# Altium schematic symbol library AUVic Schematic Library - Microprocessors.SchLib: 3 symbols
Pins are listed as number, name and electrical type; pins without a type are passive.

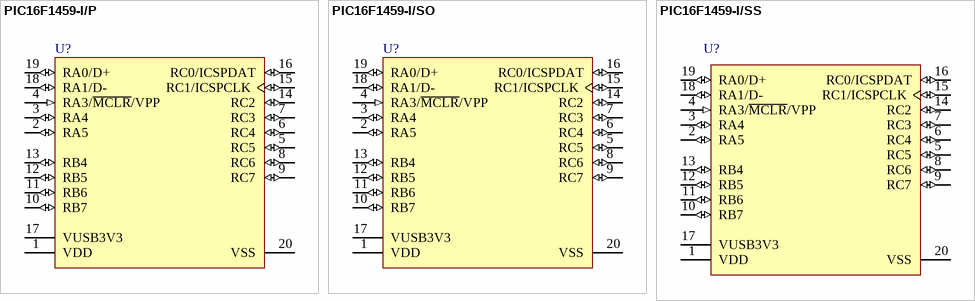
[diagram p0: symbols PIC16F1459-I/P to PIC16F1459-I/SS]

## PIC16F1459-I/P
designator U?
8-Bit Flash USB Microcontroller with XLP Technology, 48 MHz, 14 I/O, -40 to 85 degC, 20-pin PDIP (P20), Tube; Manufacturer: Microchip; PartNumber: PIC16F1459-I/P; # of A/D Channels: 9; Digital Communication: 1 -A/E/USART, 1 -MSSP(SPI/I2C); I/O Pins: 14; Internal Oscillator: 16 MHz, 31 kHz; Max. CPU Speed MHz: 48; Operation Voltage Range: 2.3V - 5.5V; Program Memory KWords: 8; RAM: 1024; Timers: 2 - 8-bit, 1 - 16-bit, 0 - 32-bit
footprint MCHP-PDIP-P20 (DIP, 20-Leads, Body 25.91x6.6mm, Pitch 2.54mm)
pins: 1 VDD (power) "Positive supply.", 2 RA5 (io), 3 RA4 (io), 4 RA3/~{MCLR}/VPP (in), 5 RC5 (io), 6 RC4 (io), 7 RC3 (io), 8 RC6 (io), 9 RC7 (io), 10 RB7 (io), 11 RB6 (io), 12 RB5 (io), 13 RB4 (io), 14 RC2 (io), 15 RC1/ICSPCLK (io), 16 RC0/ICSPDAT (io), 17 VUSB3V3 (power) "Positive supply for USB transceiver.", 18 RA1/D- (io), 19 RA0/D+ (io), 20 VSS (power) "Ground reference."

## PIC16F1459-I/SO
designator U?
8-Bit Flash USB Microcontroller with XLP Technology, 48 MHz, 14 I/O, -40 to 85 degC, 20-pin SOIC (SO20), Tube; Manufacturer: Microchip; PartNumber: PIC16F1459-I/SO; # of A/D Channels: 9; Digital Communication: 1 -A/E/USART, 1 -MSSP(SPI/I2C); I/O Pins: 14; Internal Oscillator: 16 MHz, 31 kHz; Max. CPU Speed MHz: 48; Operation Voltage Range: 2.3V - 5.5V; Program Memory KWords: 8; RAM: 1024; Timers: 2 - 8-bit, 1 - 16-bit, 0 - 32-bit
footprint MCHP-SOIC-SO20_N (SOIC, 20-Leads, Body 12.8x7.5mm, Pitch 1.27mm, IPC Medium Density)
footprint MCHP-SOIC-SO20_L (SOIC, 20-Leads, Body 12.8x7.5mm, Pitch 1.27mm, IPC High Density)
footprint MCHP-SOIC-SO20_M (SOIC, 20-Leads, Body 12.8x7.5mm, Pitch 1.27mm, IPC Low Density)
pins: 1 VDD (power) "Positive supply.", 2 RA5 (io), 3 RA4 (io), 4 RA3/~{MCLR}/VPP (in), 5 RC5 (io), 6 RC4 (io), 7 RC3 (io), 8 RC6 (io), 9 RC7 (io), 10 RB7 (io), 11 RB6 (io), 12 RB5 (io), 13 RB4 (io), 14 RC2 (io), 15 RC1/ICSPCLK (io), 16 RC0/ICSPDAT (io), 17 VUSB3V3 (power) "Positive supply for USB transceiver.", 18 RA1/D- (io), 19 RA0/D+ (io), 20 VSS (power) "Ground reference."

## PIC16F1459-I/SS
designator U?
8-Bit Flash USB Microcontroller with XLP Technology, 48 MHz, 14 I/O, -40 to 85 degC, 20-pin SSOP (SS20), Tube; Manufacturer: Microchip; PartNumber: PIC16F1459-I/SS; # of A/D Channels: 9; Digital Communication: 1 -A/E/USART, 1 -MSSP(SPI/I2C); I/O Pins: 14; Internal Oscillator: 16 MHz, 31 kHz; Max. CPU Speed MHz: 48; Operation Voltage Range: 2.3V - 5.5V; Program Memory KWords: 8; RAM: 1024; Timers: 2 - 8-bit, 1 - 16-bit, 0 - 32-bit
footprint MCHP-SSOP-SS20_N (SOP, 20-Leads, Body 7.2x5.3mm, Pitch 0.65mm, IPC Medium Density)
footprint MCHP-SSOP-SS20_L (SOP, 20-Leads, Body 7.2x5.3mm, Pitch 0.65mm, IPC High Density)
footprint MCHP-SSOP-SS20_M (SOP, 20-Leads, Body 7.2x5.3mm, Pitch 0.65mm, IPC Low Density)
pins: 1 VDD (power) "Positive supply.", 2 RA5 (io), 3 RA4 (io), 4 RA3/~{MCLR}/VPP (in), 5 RC5 (io), 6 RC4 (io), 7 RC3 (io), 8 RC6 (io), 9 RC7 (io), 10 RB7 (io), 11 RB6 (io), 12 RB5 (io), 13 RB4 (io), 14 RC2 (io), 15 RC1/ICSPCLK (io), 16 RC0/ICSPDAT (io), 17 VUSB3V3 (power) "Positive supply for USB transceiver.", 18 RA1/D- (io), 19 RA0/D+ (io), 20 VSS (power) "Ground reference."
1 alternate drawing of the same symbol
